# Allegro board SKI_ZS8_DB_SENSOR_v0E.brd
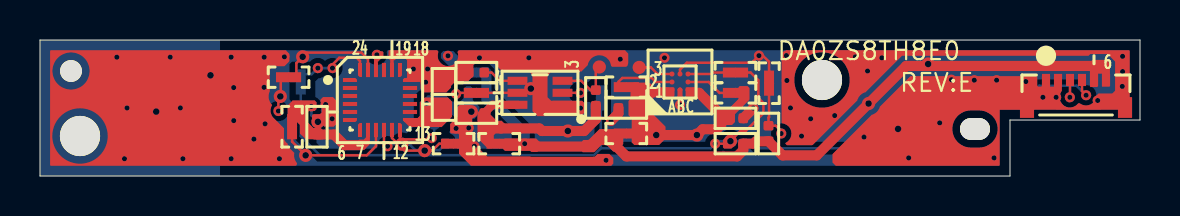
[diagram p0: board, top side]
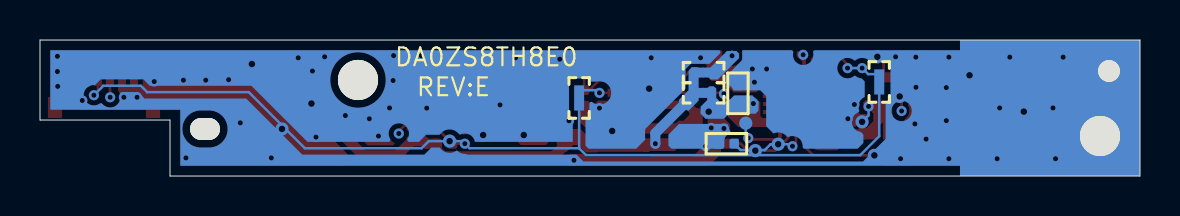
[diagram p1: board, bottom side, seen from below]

Outline 55 x 6.8 mm; copper layers: TOP, SGND, IN1, IN2, SVCC, IN3, SGND1, BOTTOM. Coordinates in mm from the lower left corner of the outline.
Outline path: 0,6.8 55,6.8 55,2.8 48.5,2.8 48.5,0 0,0 0,6.8

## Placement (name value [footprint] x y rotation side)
C1  0.1u/25v_4  [CC0402]  20.1 4.13 90 bottom
C2  10u/6.3v_6  [CC0603]  20.19 4.08 270 top
C3  0.01u/50v_4  [CC0402]  13.85 2.46 90 top
C4  0.1u_4  [CC0402]  20.68 1.62 0 bottom
C5  0.1u_4  [CC0402]  34.77 2.89 0 top
C6  0.1u_4  [CC0402]  29.31 3.39 180 top
C7  0.1u/25v_4  [CC0402]  21.82 3.14 0 top
CN5  tp_cn  [50376-00601-001-6P-L]  51.8 4.11 0 top
HOLE1  * h-c43d43n  [H-C43D43N]  1.55 5.25 0 top
HOLE2  * h-o59x43d59x43n  [H-O59X43D59X43N]  46.75 2.35 0 top
HOLE3  *spad-zs8-np  [SPAD-ZS8-NP]  4.5 3.4 180 bottom
HOLE4  * h-c79d79n  [H-C79D79N]  2 2 0 top
HOLE5  * h-c79d79n  [H-C79D79N]  39.1 4.8 0 top
NOREF  -  []  24.36 -37.27 0 top
NOREF#2  -  []  -26.44 -77.91 0 top
R1  *short_4  [SHORT0402]  21.82 4.16 0 bottom
R2  *short_4  [SHORT0402]  12.43 4.94 0 top
R3  *short_4  [SHORT0402]  21.82 5.17 0 bottom
R4  *short_4  [SHORT0402]  13.04 4.7 90 bottom
R5  *short_4  [SHORT0402]  12.61 2.46 270 top
R6  *short_4  [SHORT0402]  20.68 1.62 0 top
R7  *2.2k_4  [RC0402]  36.43 2.12 270 top
R8  *2.2k_4  [RC0402]  34.77 1.62 0 top
R11  *short_4  [SHORT0402]  36.45 4.64 90 top
R12  *short_4  [SHORT0402]  29.31 2.12 180 top
R13  *short_4  [SHORT0402]  34.77 5.17 180 top
R14  *short_4  [SHORT0402]  29.32 4.44 0 top
R15  *short_4  [SHORT0402]  34.77 4.16 180 top
R16  604k_4  [RC0402]  21.82 5.17 0 top
R17  10k/f_4  [RC0402]  27.79 3.9 270 top
R18  *short_4  [SHORT0402]  28.04 3.9 90 bottom
R19  *short_4  [SHORT0402]  22.96 1.62 0 top
R20  *short_4  [SHORT0402]  21.82 4.16 180 top
TP5164  *pad  [TP2675]  19.71 2.64 180 bottom
TP5165  *pad  [TP2675]  29.96 5.43 0 top
TP5166  *pad  [TP2675]  27.97 5.45 0 top
U1  mpu-6500  [QFN24-3X3-4]  17 3.8 0 top
U2  ak09911  [BGA8-ASAHIKASEI-AK09911C-L]  32 4.7 0 top
U3  cm32180  [OPLGA6-2_35X1_8-6]  25 4.16 0 top

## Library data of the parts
C1 C3-C7 = CC0402
C2 = CC0603
CN5 = 50376-00601-001-6P-L
HOLE1 = H-C43D43N
HOLE2 = H-O59X43D59X43N
HOLE3 = SPAD-ZS8-NP
HOLE4 HOLE5 = H-C79D79N
R1-R6 R11-R15 R18-R20 = SHORT0402
R7 R8 R16 R17 = RC0402
TP5164-TP5166 = TP2675
U1 = QFN24-3X3-4
U2 = BGA8-ASAHIKASEI-AK09911C-L
U3 = OPLGA6-2_35X1_8-6

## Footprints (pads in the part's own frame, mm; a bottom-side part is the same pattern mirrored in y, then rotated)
50376-00601-001-6P-L
  rect 0.406x0.61 smd: 1(-1.5,0.688) 2(-0.9,0.688) 3(-0.3,0.688) 4(0.3,0.688) 5(0.9,0.688) 6(1.5,0.688)
  rect 0.711x1.041 smd: 7(-2.45,-0.688) 8(2.45,-0.688)
BGA8-ASAHIKASEI-AK09911C-L
  round 0.254 smd: A1(-0.4,-0.4) A2(-0.4,0) A3(-0.4,0.4) B1(0,-0.4) B3(0,0.4) C1(0.4,-0.4) C2(0.4,0) C3(0.4,0.4)
CC0402
  custom 0.12x0.12 smd: 1(0.39,0) 2(-0.39,0)
CC0603
  rect 0.813x0.711 smd: 1(0.737,0) 2(-0.737,0)
H-C43D43N
  round 1.092 hole 1.092 unplated: (0,0)
H-C79D79N
  round 2.007 hole 2.007 unplated: (0,0)
H-O59X43D59X43N
  oval 1.499x1.092 hole 1.499x1.092 unplated: (0,0)
OPLGA6-2_35X1_8-6
  rect 0.991x0.406 smd: 1(1.125,-0.6) 2(1.125,0) 3(1.125,0.6) 4(-1.125,0.6) 5(-1.125,0) 6(-1.125,-0.6)
QFN24-3X3-4
  custom 0.05x0.05 smd: 1(-1.5,1) 6(-1.5,-1) 7(-1,-1.5) 12(1,-1.5) 13(1.5,-1) 18(1.5,1) 19(1,1.5) 24(-1,1.5)
  rect 0.711x0.203 smd: 2(-1.5,0.6) 3(-1.5,0.2) 4(-1.5,-0.2) 5(-1.5,-0.6) 14(1.5,-0.6) 15(1.5,-0.2) 16(1.5,0.2) 17(1.5,0.6)
  rect 0.203x0.711 smd: 8(-0.6,-1.5) 9(-0.2,-1.5) 10(0.2,-1.5) 11(0.6,-1.5) 20(0.6,1.5) 21(0.2,1.5) 22(-0.2,1.5) 23(-0.6,1.5)
RC0402
  custom 0.12x0.12 smd: 1(0.39,0) 2(-0.39,0)
SHORT0402
  rect 0.648x0.5 smd: 1(-0.39,0) 2(0.39,0)
SPAD-ZS8-NP
  custom 1.7x1.7 smd: 1(0,0)
TP2675
  round 0.66 smd: 1(0,0)

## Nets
+3V3: CN5.5 CN5.6 R1.2 R3.2 R7.1 R8.1 R12.2 R19.2
+3V3_LS: C7.1 R17.1 R19.1 U3.6
+V3.3S_GYRO: C1.2 C2.1 R1.1 U1.13
GND: C1.1 C2.2 C3.1 C4.1 C5.1 C6.1 C7.2 CN5.1 CN5.2 CN5.7 CN5.8 HOLE3.1 R6.2 R16.2 U1.18 U1.20 U2.B1 U3.1
VDDIO: C3.2 R3.1 R5.1 U1.8 U1.22
6500_REGOUT: C4.2 U1.10
+ECOM_VDD: C5.2 C6.2 R12.1 R14.2 R15.1 U2.A1 U2.C1
ADO: R5.2 U1.9
ALS_INT#: R17.2 TP5166.1 U3.3
ECOM_RST: R15.2 U2.C2
GYRO_INT1: TP5164.1 U1.12
I2C_ECOM_SCL: R11.2 U2.B3
I2C_ECOM_SDA: R13.2 U2.C3
I2C_GYRO_SCL: R2.2 U1.23
I2C_GYRO_SDA: R4.2 U1.24
LIGHT_SCL: R20.1 U3.5
LIGHT_SDA: R18.2 U3.2
SCL_TO_EC: CN5.3 R2.1 R7.2 R11.1 R20.2
SDA_TO_EC: CN5.4 R4.1 R8.2 R13.1 R18.1
TST: TP5165.1 U2.A3
N38237819: R6.1 U1.11
N38242499: R14.1 U2.A2
N38259389: R16.1 U3.4

Pads without a net: U1 1 2 3 4 5 6 7 14 15 16 17 19 21

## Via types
v1: diameter 0.508, hole 0.254, TOP to BOTTOM, 73 vias
v2: diameter 0.66, hole 0.33, TOP to BOTTOM, 17 vias

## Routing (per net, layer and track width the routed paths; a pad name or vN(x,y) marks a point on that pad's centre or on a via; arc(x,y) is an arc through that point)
+3V3: length 32.5
  TOP w0.508: 27.52,1.47 24.72,1.47 ; 28.73,1.56 29.31,0.98 34.86,0.98 35.16,1.29 R8.1 35.68,1.62 35.8,1.73 R7.1 37.13,1.03 38.84,1.03 v2(41.43,3.62) 43.31,5.5 52.85,5.5
  BOTTOM w0.508: v1(24.23,1.62) 24.23,2.14 22.71,3.66
+3V3_LS: length 7.5
  TOP w0.406: C7.1 22.63,3.56 U3.6
  TOP w0.508: R17.1 27.79,2.84 27.21,2.25 v2(26.39,2.25) 25.1,2.25 24.97,2.38 23.06,2.38
+V3.3S_GYRO:
  vias: v1(19.33,3.62) v2(21.57,3.22)
GND: length 2.8
  TOP w0.178: U1.20 17.6,5.88
  TOP w0.254: U2.B1 v1(32,3.56)
  TOP w0.508: C6.1 28.92,3.13 v1(28.55,2.76) ; v1(35.66,3.39) 35.66,3.39 C5.1
  vias: v1(3.84,5.94) v1(4.22,0.86) v1(4.35,3.4) v1(6.51,5.94) v1(7.02,3.4) v1(7.14,0.86) v1(9.56,5.94) v1(9.56,0.86) v1(9.68,4.42) v1(9.68,2.77) v1(10.7,1.84) v1(11.21,5.94) v1(11.2,4.44) v1(11.25,2.61) v1(11.97,0.86) v1(12.22,5.96) v1(14.28,3.57) v1(14.61,2.86) v1(18.67,5.35) v1(19.28,4.69) v1(19.38,5.35) v1(20.8,2.38) v1(21.44,2.4) v1(21.72,1.49) v1(21.97,5.91) v1(24.44,5.91) v1(27.03,3.39) v1(28.3,0.79) v1(29.01,5.84) v1(31.22,5.91) v1(37.32,6.02) v1(37.34,4.77) v1(37.52,3.4) v1(38.08,2) v1(38.53,2.86) v1(39.73,3.02) v1(40.77,5.96) v1(41.2,1.95) v1(41.38,5.25) v1(42.09,5.91) v1(43.44,0.9) v1(44.99,2.66) v1(45.57,4.82) v1(46.71,4.79) v1(47.7,0.9) v1(47.83,4.79) v1(49.29,4.72) v1(50.15,3.94) v1(50.81,3.94) v1(52.88,3.77) v1(54.13,5.98) v1(54.13,5.22) v1(54.11,4.48) v2(5.81,3.22) v2(8.52,5.04) v2(24.54,4.37) v2(42.9,2.35) v2(44.41,5.6)
VDDIO: length 17.2
  TOP w0.508: 16.08,1.54 15.23,1.54 14.7,2.07 C3.2
  IN1 w0.508: v1(13.57,3.48) 13.58,3.47 13.58,2.63 14.01,2.2 18.98,2.2 20.09,3.32 20.09,4.49 20.4,4.79 v1(20.4,6.01) 17.42,6.01
  BOTTOM w0.127: v2(13.9,2.71) 13.57,3.03 v1(13.57,3.48)
  vias: v1(16.84,6.06)
6500_REGOUT: length 4.1
  TOP w0.127: v1(17.38,1.49) 17.2,1.67 U1.10
  BOTTOM w0.127: C4.2 19.97,1.3 18.76,1.3 18.47,1.59 v2(18.09,1.59) 17.48,1.59 v1(17.38,1.49)
+ECOM_VDD: length 5.8
  TOP w0.508: 30.62,4.18 31.37,4.18 ; v2(30.81,2.05) v2(32.84,2.05) 33.13,2.34 33.83,2.34 34.07,2.57 ; 33.8,3.32 32.96,4.16 32.62,4.16
ADO: length 5.8
  TOP w0.127: U1.9 16.8,1.5 16.33,1.03 v2(13.28,1.03) 13.24,1.07 13.24,1.08 12.61,1.72 R5.2
ALS_INT#: length 3.1
  TOP w0.127: U3.3 27.06,4.76 27.53,4.29 R17.2 27.79,5.27 TP5166.1
ECOM_RST: length 2.2
  TOP w0.127: R15.2 33.98,4.16 33.43,4.7 U2.C2
GYRO_INT1: length 2.8
  TOP w0.127: U1.12 18,1.9 18.07,1.83 19.52,1.83 v1(19.59,1.9)
  BOTTOM w0.127: TP5164.1 19.71,2.02 v1(19.59,1.9)
I2C_ECOM_SCL: length 5.8
  TOP w0.127: U2.B3 32,5.32 32.34,5.66 35.59,5.66 v1(35.95,6.02) 36.14,6.02 36.45,5.71 R11.2
I2C_ECOM_SDA: length 2
  TOP w0.127: R13.2 33.64,5.17 33.56,5.1 U2.C3
I2C_GYRO_SCL: length 5.2
  TOP w0.127: U1.23 16.4,5.84 16.07,6.17 13.34,6.17 v2(13.13,5.96) 12.82,5.64 R2.2
I2C_GYRO_SDA: length 3.9
  TOP w0.127: U1.24 16,5.75 15.83,5.91 14.97,5.91 14.62,5.57 v1(14.62,5.39)
  BOTTOM w0.127: v1(14.62,5.39) v1(13.89,5.39) 13.59,5.09 R4.2
LIGHT_SCL: length 1.7
  TOP w0.127: R20.1 22.78,4.16 22.79,4.16 U3.5
LIGHT_SDA: length 2
  TOP w0.127: v1(27.03,4.16) 27.02,4.16 U3.2
  BOTTOM w0.127: R18.2 27.16,4.29 v1(27.03,4.16)
SCL_TO_EC: length 51.5
  TOP w0.127: R20.2 20.86,4.16 v1(20.8,4.11) ; R11.1 36.45,2.95 36.43,2.92 R7.2 36.79,2.51 37.06,2.24 v1(37.06,2.12) ; v1(11.92,3.25) 11.92,3.88 v2(12.02,3.98) 12.04,4 R2.1 ; v1(51.49,3.94) 51.5,3.94 CN5.3
  IN1 w0.127: v1(51.49,3.94) 51.49,4.24 51.21,4.52 49.94,4.52 49.61,4.19 44.84,4.19 41.99,1.34 37.85,1.34 v1(37.06,2.12) 35.53,2.12 35.47,2.18 22.73,2.18 v1(20.8,4.11) 20.67,4.11 20.54,3.97 20.54,3.13 20.14,2.74 20.14,1.83 19.36,1.04 14.13,1.04 v1(11.92,3.25)
SDA_TO_EC: length 52.6
  TOP w0.127: v1(52.31,4.04) 52.1,4.24 CN5.4 ; v1(33.76,1.62) R8.2 35.02,2.25 35.28,2.25 36.17,3.14 36.17,3.65 35.92,3.9 35.92,4.79 35.54,5.17 R13.1
  BOTTOM w0.127: v1(52.31,4.04) 51.83,4.51 49.96,4.51 49.64,4.19 44.56,4.19 41.76,1.39 35.92,1.39 35.56,1.74 v2(34.52,1.74) 33.89,1.74 v1(33.76,1.62) 33.53,1.39 28.04,1.39 ; R18.1 28.04,1.39 ; 28.04,1.39 27.7,1.04 13.98,1.04 13.04,1.99 R4.1
TST: length 1.8
  TOP w0.127: U2.A3 30.87,5.1 30.54,5.43 TP5165.1
N38237819: length 3.5
  TOP w0.127: R6.1 19.96,1.62 19.62,1.27 v2(19.23,1.27) 18.23,1.27 17.6,1.9 U1.11
N38242499: length 3.1
  TOP w0.127: U2.A2 30.79,4.7 30.59,4.9 29.12,4.9 28.93,4.72 R14.1
N38259389: length 1.8
  TOP w0.127: U3.4 22.99,4.76 22.58,5.17 R16.1

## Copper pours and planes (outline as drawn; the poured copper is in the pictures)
+3V3 on TOP (solid shape): 24.98,1.7 24.98,1.32 24.86,1.2 24.56,1.2 24.51,1.26 23.25,1.26 23.15,1.35 23.15,1.8 23.23,1.88 24.8,1.88
+3V3 on TOP (solid shape): 53.5,5.62 53.5,4.49 53.48,4.47 53.11,4.47 53.1,4.48 53.1,5.1 53.09,5.12 52.92,5.12 52.9,5.11 52.9,4.49 52.86,4.45 52.53,4.45 52.5,4.48 52.5,5.44 52.49,5.66 52.64,5.81 53.31,5.81
+3V3 on TOP (solid shape): 29.16,2.12 29.16,1.59 28.79,1.21 28.67,1.21 28.33,1.55 28.07,1.55 27.71,1.19 27.13,1.19 27.11,1.2 27.11,1.74 27.17,1.8 27.42,1.8 27.97,2.35 28.09,2.35 28.94,2.35
+3V3 on BOTTOM (solid shape): 22.57,5.27 22.57,4.29 23.05,3.81 23.05,3.68 22.64,3.27 22.56,3.27 22.07,3.77 22.07,5.37 22.13,5.44 22.4,5.44
+3V3_LS on TOP (solid shape): 22.53,3.32 22.53,3.06 22.84,2.76 23.09,2.76 23.24,2.61 23.24,2.25 23.11,2.12 22.77,2.12 22.69,2.04 22.69,1.45 22.63,1.39 22.38,1.39 21.87,1.9 21.87,3.17 22.07,3.37 22.49,3.37
+V3.3S_GYRO on TOP (solid shape): 20.6,3.72 20.6,2.96 20.09,2.45 18.48,2.45 18.15,2.78 18.15,2.88 18.17,2.9 18.87,2.9 18.98,3 18.98,3.68 19.23,3.93 20.4,3.93
+V3.3S_GYRO on BOTTOM (solid shape): 21.64,4.38 21.64,3.8 21.96,3.48 21.97,3.48 21.97,3.11 21.72,2.86 20.8,2.86 20.55,3.11 19.23,3.11 19.08,3.27 19.08,3.72 19.38,4.03 20.3,4.03 20.6,3.72 21.01,3.72 21.21,3.93 21.21,4.38 21.31,4.49 21.53,4.49
GND on TOP (solid shape): 14.89,3.71 14.89,2.66 14.69,2.47 14.22,2.47 14.07,2.62 13.72,2.62 13.62,2.72 13.62,2.99 13.7,3.07 13.98,3.07 14.08,3.17 14.08,3.45 14.07,3.58 14.02,3.71 14.02,3.82 14.15,3.95 14.65,3.95
GND on TOP (solid shape): 21.65,3.43 21.65,3.41 21.65,3.31 21.63,3.29 21.62,3.27 21.62,3.25 21.62,1.81 21.62,1.79 21.63,1.78 22.02,1.38 22.02,1.34 22.03,1.32 22.04,1.3 22.35,0.99 22.36,0.98 22.38,0.98 24.49,0.98 24.53,0.96 27.71,0.96 27.73,0.97 27.74,0.98 27.87,1.11 28.47,1.11 28.66,0.91 28.66,0.62 28.56,0.51 21.55,0.51 20.95,1.11 20.95,2.07 20.59,2.12 20.57,2.12 20.56,2.14 20.51,2.19 20.51,2.58 20.84,2.93 20.85,2.95 20.86,2.97 20.86,3.42 20.96,3.54 20.98,3.55 21.5,3.55
GND on TOP (solid shape): 19.81,6.29 19.9,6.25 19.91,6.16 20.4,5.5 20.88,6.16 20.9,6.25 20.98,6.29 29.24,6.29 29.41,6.13 29.41,5.63 29.39,5.58 29.38,5.52 29.32,5.46 28.6,5.46 28.55,5.51 27.98,6.03 27.39,5.54 27.06,5.22 25.57,5.22 25.37,5.03 25.37,3.94 25.56,3.76 27.11,3.76 27.21,3.66 27.26,3.62 27.28,3.56 27.28,3.22 27.05,2.99 24.86,2.99 24.62,3.23 24.62,5.05 24.45,5.22 23.12,5.22 22.66,5.68 22.07,5.68 22.03,5.67 21.81,5.67 21.67,5.54 21.67,5 21.43,4.75 20.8,4.75 20.55,4.51 20.55,4.41 20.32,4.18 19.19,4.18 19.02,4.35 19.02,4.68 19,4.7 18.15,4.7 18.15,4.71 18.15,4.82 18.22,4.9 18.33,4.9 18.35,4.92 18.35,5.79 18.29,5.85 17.8,5.85 17.74,5.79 17.51,5.79 17.42,5.87 17.42,6.24 17.44,6.28 17.48,6.29
GND on TOP (solid shape): outline of 219 points within 0.51,0.51 12.85,6.29
GND on TOP (solid shape): outline of 306 points within 37.08,0.51 54.49,6.29
GND on BOTTOM (solid shape): 23.58,2.07 23.58,1.52 23.42,1.36 20.88,1.36 20.81,1.39 20.78,1.77 20.72,1.97 20.54,2.1 20.48,2.17 20.5,2.26 20.58,2.4 20.62,2.56 20.63,2.58 20.65,2.61 23.04,2.61
GND on BOTTOM (solid shape): outline of 853 points within 0.51,0.51 54.49,6.29
GND on SGND (solid shape): outline of 323 points within 0.51,0.51 54.49,6.29
GND on IN1 (solid shape): outline of 759 points within 0.51,0.51 54.49,6.29
GND on IN2 (solid shape): outline of 1086 points within 0.51,0.51 54.49,6.29
GND on SVCC (solid shape): outline of 323 points within 0.51,0.51 54.49,6.29
GND on IN3 (solid shape): outline of 1089 points within 0.51,0.51 54.49,6.29
GND on SGND1 (solid shape): outline of 323 points within 0.51,0.51 54.49,6.29
VDDIO on TOP (solid shape): 13.83,3.68 13.83,3.35 13.73,3.25 13.45,3.25 13.34,3.13 13.34,2.74 13.68,2.4 14.04,2.4 14.15,2.28 14.15,1.87 14.12,1.83 13.28,1.83 12.99,2.12 12.99,2.55 12.85,2.69 12.47,2.69 12.38,2.78 12.38,3.52 12.64,3.78 13.73,3.78
VDDIO on BOTTOM (solid shape): 21.54,5.37 21.54,4.9 21.46,4.82 21.11,4.82 20.04,5.89 20.04,6.12 20.18,6.25 20.65,6.25
+ECOM_VDD on TOP (solid shape): 30.67,4.48 30.67,3.08 31.28,2.46 31.28,1.87 30.96,1.55 29.71,1.55 29.59,1.67 29.59,2.88 29.42,3.04 29.42,3.75 29.52,3.85 29.52,4.51 29.69,4.67 30.48,4.67
+ECOM_VDD on TOP (solid shape): 35.48,4.4 35.48,3.91 35.48,3.82 34.75,3.09 34.75,2.7 34.6,2.55 33.93,2.55 33.69,2.79 33.69,3.29 33.78,3.37 34.44,3.37 34.92,3.85 34.92,4.44 34.98,4.5 35.38,4.5

Small or netless copper shapes (teardrops, artwork), in the pictures only: 4 on TOP, 1 on IN1

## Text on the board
Ref Des/Silkscreen Bottom: REV:E | DA0ZS8TH8E0
Ref Des/Silkscreen Top: DA0ZS8TH8E0 | REV:E
User.45: FIGURE | TYPE | Circle | Oblong | SIZE | 10.0 | 43.0 | 79.0 | 59.0x43.0 | DRILL CHART: TOP to BOTTOM | ALL UNITS ARE IN MILS | PLATED | NON-PLATED | ROTATION | - | 0.000 | QTY | 71 | 1 | 2 | 74 | TOTAL HOLES:
